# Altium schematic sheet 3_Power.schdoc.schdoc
size 431 x 309 mm; Symbol: Sheet-Symbol_A3; Device: Sheet-Symbol_A3; Company: 嘉立创EDA; Version: V1.0; Page Size: A3; @Project Name: RTL8367S_RTL8213B; @Page Count: 5; @Update Date: 2022-12-30; @Create Date: 2022-10-17; @Schematic Name: Schematic1; @Page No: 3; @Page Name: Power
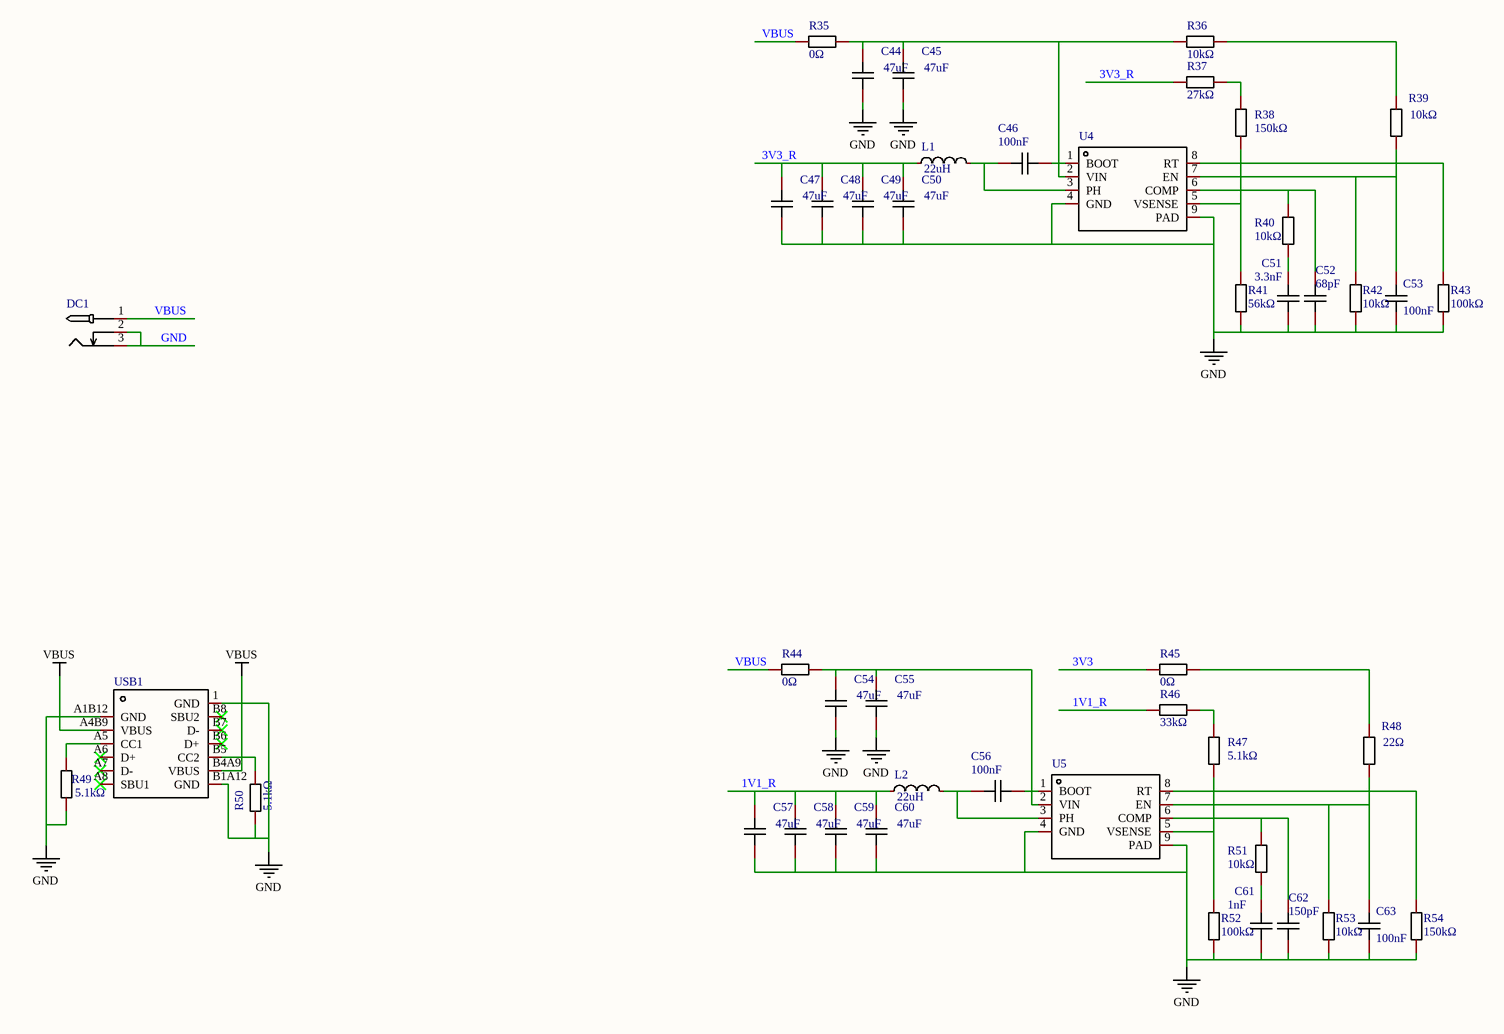
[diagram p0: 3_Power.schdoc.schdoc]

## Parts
C44  value 47uF  [C1206]  (hidden comment: CL31A476MPHNNNE)
C45  value 47uF  [C1206]  (hidden comment: CL31A476MPHNNNE)
C46  value 100nF  [C0603]  (hidden comment: CC0603KRX7R9BB104)
C47  value 47uF  [C1206]  (hidden comment: CL31A476MPHNNNE)
C48  value 47uF  [C1206]  (hidden comment: CL31A476MPHNNNE)
C49  value 47uF  [C1206]  (hidden comment: CL31A476MPHNNNE)
C50  value 47uF  [C1206]  (hidden comment: CL31A476MPHNNNE)
C51  value 3.3nF  [C0402]  (hidden comment: CL05B332KB5NNNC)
C52  value 68pF  [C0402]  (hidden comment: CL05C680JB5NNNC)
C53  value 100nF  [C0402_NEW]  (hidden comment: CL05B104KO5NNNC)
C54  value 47uF  [C1206]  (hidden comment: CL31A476MPHNNNE)
C55  value 47uF  [C1206]  (hidden comment: CL31A476MPHNNNE)
C56  value 100nF  [C0603]  (hidden comment: CC0603KRX7R9BB104)
C57  value 47uF  [C1206]  (hidden comment: CL31A476MPHNNNE)
C58  value 47uF  [C1206]  (hidden comment: CL31A476MPHNNNE)
C59  value 47uF  [C1206]  (hidden comment: CL31A476MPHNNNE)
C60  value 47uF  [C1206]  (hidden comment: CL31A476MPHNNNE)
C61  value 1nF  [C0402]  (hidden comment: 0402B102K500NT)
C62  value 150pF  [C0402]  (hidden comment: 0402B151K500NT)
C63  value 100nF  [C0402_NEW]  (hidden comment: CL05B104KO5NNNC)
DC1  DC-005_2.5  [DC-IN-TH_DC005]  (value not drawn)
L1  value 22uH  [IND-SMD_L5.0-W5.0_LVS505040]  (hidden comment: VLS5045EX-220M)
L2  value 22uH  [IND-SMD_L5.0-W5.0_LVS505040]  (hidden comment: VLS5045EX-220M)
R35  value 0Ω  [R0603]  (hidden comment: 0603WAF0000T5E)
R36  value 10kΩ  [R0402]  (hidden comment: 0402WGF1002TCE)
R37  value 27kΩ  [R0402]  (hidden comment: 0402WGF2702TCE)
R38  value 150kΩ  [R0402]  (hidden comment: 0402WGF1503TCE)
R39  value 10kΩ  [R0402]  (hidden comment: 0402WGF1002TCE)
R40  value 10kΩ  [R0402]  (hidden comment: 0402WGF1002TCE)
R41  value 56kΩ  [R0402]  (hidden comment: 0402WGF5602TCE)
R42  value 10kΩ  [R0402]  (hidden comment: 0402WGF1002TCE)
R43  value 100kΩ  [R0402]  (hidden comment: 0402WGF1003TCE)
R44  value 0Ω  [R0603]  (hidden comment: 0603WAF0000T5E)
R45  value 0Ω  [R0402]  (hidden comment: 0402WGF0000TCE)
R46  value 33kΩ  [R0402]  (hidden comment: 0402WGF3302TCE)
R47  value 5.1kΩ  [R0402]  (hidden comment: 0402WGF5101TCE)
R48  value 22Ω  [R0402]  (hidden comment: 0402WGF220JTCE)
R49  value 5.1kΩ  [R0402]  (hidden comment: 0402WGF5101TCE)
R50  value 5.1kΩ  [R0402]  (hidden comment: 0402WGF5101TCE)
R51  value 10kΩ  [R0402]  (hidden comment: 0402WGF1002TCE)
R52  value 100kΩ  [R0402]  (hidden comment: 0402WGF1003TCE)
R53  value 10kΩ  [R0402]  (hidden comment: 0402WGF1002TCE)
R54  value 150kΩ  [R0402]  (hidden comment: 0402WGF1503TCE)
U4  TPS54335ADDAR  [SOP-8_L4.9-W3.9-P1.27-LS6.0-BL-EP-1]  (value not drawn)
U5  TPS54335ADDAR  [SOP-8_L4.9-W3.9-P1.27-LS6.0-BL-EP-1]  (value not drawn)
USB1  TYPE-C-31-M-08B  [USB-C-SMD_TYPE-C-31-M-08B]  (value not drawn)

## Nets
GND: C44.1 C45.1 C47.2 C48.2 C49.2 C50.2 C51.1 C52.1 C53.1 C54.1 C55.1 C57.2 C58.2 C59.2 C60.2 C61.1 C62.1 C63.1 DC1.2 DC1.3 R41.1 R42.1 R43.2 R49.1 R50.1 R52.1 R53.1 R54.2 U4.4(GND) U4.9(PAD) U5.4(GND) U5.9(PAD) USB1.1(GND) USB1.A1B12(GND) USB1.B1A12(GND)
VBUS: DC1.1 R35.1 R44.1 USB1.A4B9(VBUS) USB1.B4A9(VBUS)
1V1_R: C57.1 C58.1 C59.1 C60.1 L2.1 R46.1
3V3: R45.1
3V3_R: C47.1 C48.1 C49.1 C50.1 L1.1 R37.1
NetC44_2: C44.2 C45.2 R35.2 R36.1 U4.2(VIN)
NetC46_1: C46.1 L1.2 U4.3(PH)
NetC46_2: C46.2 U4.1(BOOT)
NetC51_2: C51.2 R40.1
NetC52_2: C52.2 R40.2 U4.6(COMP)
NetC53_2: C53.2 R39.1 R42.2 U4.7(EN)
NetC54_2: C54.2 C55.2 R44.2 U5.2(VIN)
NetC56_1: C56.1 L2.2 U5.3(PH)
NetC56_2: C56.2 U5.1(BOOT)
NetC61_2: C61.2 R51.1
NetC62_2: C62.2 R51.2 U5.6(COMP)
NetC63_2: C63.2 R48.1 R53.2 U5.7(EN)
NetR36_2: R36.2 R39.2
NetR37_2: R37.2 R38.2
NetR38_1: R38.1 R41.2 U4.5(VSENSE)
NetR43_1: R43.1 U4.8(RT)
NetR45_2: R45.2 R48.2
NetR46_2: R46.2 R47.2
NetR47_1: R47.1 R52.2 U5.5(VSENSE)
NetR49_2: R49.2 USB1.A5(CC1)
NetR50_2: R50.2 USB1.B5(CC2)
NetR54_1: R54.1 U5.8(RT)

Not connected (* = marked no-connect by the designer): USB1 A6(D+)* A7(D-)* A8(SBU1)* B6(D+)* B7(D-)* B8(SBU2)*

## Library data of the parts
C44 C45 C47-C50 C54 C55 C57-C60 = CL31A476MPHNNNE: Manufacturer: SAMSUNG(三星); Symbol: C1210X7R475K630NT; Add into BOM: yes; Tolerance: ±20%; Voltage Rated: 10V; Temperature Coefficient: X5R; Description: 容值:47uF;精度:±20%;额定电压:10V;材质(温度系数):X5R;
C46 C56 = CC0603KRX7R9BB104: Manufacturer: YAGEO(国巨); Symbol: C1210X7R475K630NT; Add into BOM: yes; Tolerance: ±10%; Voltage Rated: 50V; Temperature Coefficient: X7R; Description: 容值:100nF;精度:±10%;额定电压:50V;材质(温度系数):X7R;
C51 = CL05B332KB5NNNC: Manufacturer: SAMSUNG(三星); Symbol: C1210X7R475K630NT; Add into BOM: yes; Tolerance: ±10%; Voltage Rated: 50V; Temperature Coefficient: X7R; Description: 容值:3.3nF;精度:±10%;额定电压:50V;材质(温度系数):X7R;
C52 = CL05C680JB5NNNC: Manufacturer: SAMSUNG(三星); Symbol: C1210X7R475K630NT; Add into BOM: yes; Tolerance: ±5%; Voltage Rated: 50V; Temperature Coefficient: C0G; Description: 容值:68pF;精度:±5%;额定电压:50V;材质(温度系数):C0G;
C53 C63 = CL05B104KO5NNNC: Manufacturer: SAMSUNG(三星); Symbol: C1210X7R475K630NT; Add into BOM: yes; Tolerance: ±10%; Voltage Rated: 16V; Temperature Coefficient: X7R; Description: 容值:100nF;精度:±10%;额定电压:16V;材质(温度系数):X7R;
C61 = 0402B102K500NT: Manufacturer: FH(风华); Symbol: C1210X7R475K630NT; Add into BOM: yes; Tolerance: ±10%; Voltage Rated: 50V; Temperature Coefficient: X7R; Description: 容值:1nF;精度:±10%;额定电压:50V;材质(温度系数):X7R;
C62 = 0402B151K500NT: Manufacturer: FH(风华); Symbol: C1210X7R475K630NT; Add into BOM: yes; Tolerance: ±10%; Voltage Rated: 50V; Temperature Coefficient: X7R; Description: 容值:150pF;精度:±10%;额定电压:50V;材质(温度系数):X7R;
DC1 = DC-005_2.5: Symbol: DC电源接口; Convert to PCB: yes; Add into BOM: no; Description: 连接器类型:DC电源插座;触点内径:2.5mm;触点外径:6.4mm;额定电流:500mA;额定电压:30V;
L1 L2 = VLS5045EX-220M: Manufacturer: TDK; Symbol: SDFL1608S100KTF; Add into BOM: yes; Tolerance: ±20%; Rated Current: 1.8A; DC Resistance (DCR): 125mΩ; Description: 电感值:22uH;精度:±20%;额定电流:1.8A;直流电阻(DCR):125mΩ;
R35 R44 = 0603WAF0000T5E: Manufacturer: UNI-ROYAL(厚声); Symbol: 电阻; Add into BOM: yes; Tolerance: ±1%; Power(Watts): 100mW; Overload Voltage (Max): 75V; Description: 温度系数:-;精度:±1%;阻值:0Ω;功率:1/10W;最大工作电压:75V;工作温度范围:-55℃~+155℃;
R36 R39 R40 R42 R51 R53 = 0402WGF1002TCE: Manufacturer: UNI-ROYAL(厚声); Symbol: 电阻; Add into BOM: yes; Tolerance: ±1%; Power(Watts): 62.5mW; Temperature Coefficient: ±100ppm/℃; Overload Voltage (Max): 50V; Description: 电阻类型:厚膜电阻;阻值:10kΩ;精度:±1%;功率:62.5mW;温度系数:±100ppm/℃;最大工作电压:50V;工作温度范围:-55℃~+155℃;
R37 = 0402WGF2702TCE: 电阻类型:厚膜电阻;阻值:75kΩ;精度:±1%;功率:62.5mW;温度系数:±100ppm/℃;最大工作电压:50V;工作温度范围:-55℃~+155℃;; Manufacturer: UNI-ROYAL(厚声); Symbol: 电阻; Add into BOM: yes; Tolerance: ±1%; Power(Watts): 62.5mW; Overload Voltage (Max): 50V
R38 = 0402WGF1503TCE: 阻值:150kΩ;精度:±1%;功率:1/16W;温度系数:±100ppm/℃;最大工作电压:50V;工作温度范围:-55℃~+155℃;; Manufacturer: UNI-ROYAL(厚声); Symbol: 电阻; Add into BOM: yes; Tolerance: ±1%; Power(Watts): 1/16W; Overload Voltage (Max): 50V
R41 = 0402WGF5602TCE: Manufacturer: UNI-ROYAL(厚声); Symbol: 电阻; Add into BOM: yes; Tolerance: ±1%; Power(Watts): 62.5mW; Temperature Coefficient: ±100ppm/℃; Overload Voltage (Max): 50V; Description: 电阻类型:厚膜电阻;阻值:56kΩ;精度:±1%;功率:62.5mW;温度系数:±100ppm/℃;最大工作电压:50V;工作温度范围:-55℃~+155℃;
R43 R52 = 0402WGF1003TCE: Manufacturer: UNI-ROYAL(厚声); Symbol: 电阻; Add into BOM: yes; Tolerance: ±1%; Power(Watts): 62.5mW; Temperature Coefficient: ±100ppm/℃; Overload Voltage (Max): 50V; Description: 电阻类型:厚膜电阻;阻值:100kΩ;精度:±1%;功率:62.5mW;温度系数:±100ppm/℃;最大工作电压:50V;工作温度范围:-55℃~+155℃;
R45 = 0402WGF0000TCE: Manufacturer: UNI-ROYAL(厚声); Symbol: 电阻; Add into BOM: yes; Tolerance: ±1%; Power(Watts): 62.5mW; Temperature Coefficient: ±800ppm/℃; Overload Voltage (Max): 50V; Description: 电阻类型:厚膜电阻;阻值:0Ω;精度:±1%;功率:62.5mW;温度系数:±800ppm/℃;最大工作电压:50V;工作温度范围:-55℃~+155℃;
R46 = 0402WGF3302TCE: Manufacturer: UNI-ROYAL(厚声); Symbol: 电阻; Add into BOM: yes; Tolerance: ±1%; Power(Watts): 62.5mW; Temperature Coefficient: ±100ppm/℃; Overload Voltage (Max): 50V; Description: 电阻类型:厚膜电阻;阻值:33kΩ;精度:±1%;功率:62.5mW;温度系数:±100ppm/℃;最大工作电压:50V;工作温度范围:-55℃~+155℃;
R47 = 0402WGF5101TCE: Manufacturer: UNI-ROYAL(厚声); Symbol: 电阻; Add into BOM: yes; Tolerance: ±1%; Power(Watts): 62.5mW; Temperature Coefficient: ±100ppm/℃; Overload Voltage (Max): 50V; Description: 电阻类型:厚膜电阻;阻值:5.1kΩ;精度:±1%;功率:62.5mW;温度系数:±100ppm/℃;最大工作电压:50V;工作温度范围:-55℃~+155℃;
R48 = 0402WGF220JTCE: Manufacturer: UNI-ROYAL(厚声); Symbol: 电阻; Add into BOM: yes; Tolerance: ±1%; Power(Watts): 62.5mW; Temperature Coefficient: ±200ppm/℃; Overload Voltage (Max): 50V; Description: 电阻类型:厚膜电阻;阻值:22Ω;精度:±1%;功率:62.5mW;温度系数:±200ppm/℃;最大工作电压:50V;工作温度范围:-55℃~+155℃;
R49 R50 = 0402WGF5101TCE: 电阻类型:薄膜电阻;阻值:10kΩ;精度:±0.5%;功率:63mW;温度系数:±25ppm/;最大工作电压:25V;工作温度范围:-55~+155;; Manufacturer: UNI-ROYAL(厚声); Symbol: tr0402d10kq1025; Add into BOM: yes; Tolerance: ±1%; Power(Watts): 62.5mW; Temperature Coefficient: ±100ppm/℃; Overload Voltage (Max): 50V
R54 = 0402WGF1503TCE: Manufacturer: UNI-ROYAL(厚声); Symbol: 电阻; Add into BOM: yes; Tolerance: ±1%; Power(Watts): 62.5mW; Temperature Coefficient: ±100ppm/℃; Overload Voltage (Max): 50V; Description: 电阻类型:厚膜电阻;阻值:150kΩ;精度:±1%;功率:62.5mW;温度系数:±100ppm/℃;最大工作电压:50V;工作温度范围:-55℃~+155℃;
U4 U5 = TPS54335ADDAR: 功能类型:降压型;同步整流:是;输出类型:可调;输出通道数:1;拓扑结构:降压式;输入电压:4.5V~28V;输出电压:800mV~24V;输出电流(最大值):3A;开关频率:1.5MHz;工作温度:-40℃~+150℃@(TJ);; Manufacturer: TI(德州仪器); Add into BOM: yes; Function: 降压型; Synchronous Rectification: 是; Output Type: 可调; Number of Outputs: 1; Topology: 降压式; Output Current (Max): 3A; Switching Frequency: 1.5MHz
USB1 = TYPE-C-31-M-08B: 连接器类型:Type-C;标准:-;公母:母座;触点数量:16;端口数量:1;安装方式:卧贴;额定电流 - 电源:5A;工作温度范围:-30~+80;; Manufacturer: 韩国韩荣; Add into BOM: no; Convert to PCB: yes; Connector Type: Type-C; Gender: 母座; Number of Contacts: 16; Number of Ports: 1; Current Rating - Power (Max): 5A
